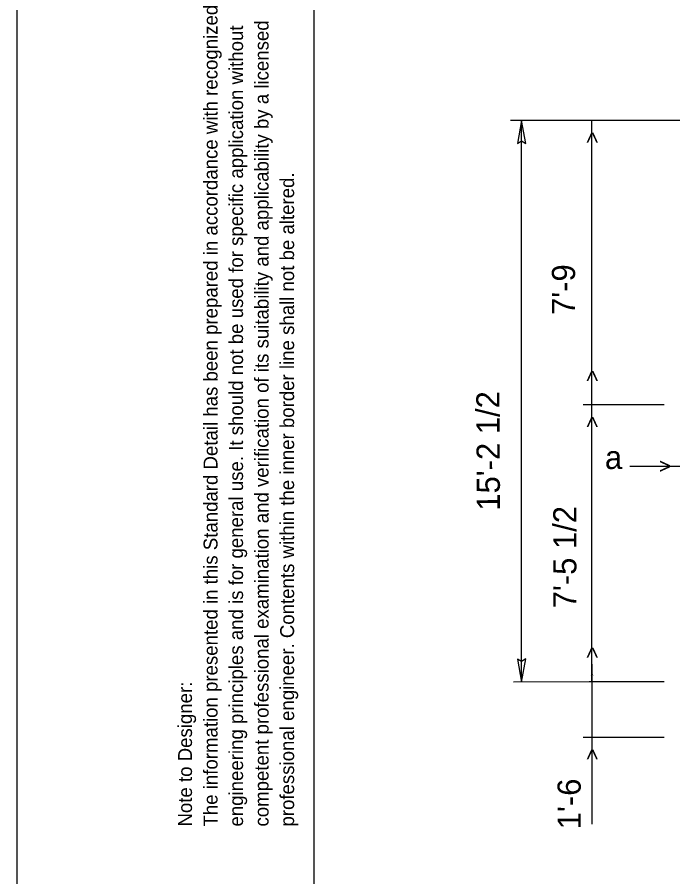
# Model space of a CAD drawing. Extents: x -0.08 to 2.83, y -0.03 to 1.92.
# Drawn here: x 0 to 0.368, y 0.5669 to 1.0496 of the extents above; entities that cross this region are included whole.
import ezdxf

# ---------------------------------------------------------------- set-up
doc = ezdxf.new("R2010")
doc.units = 0
for name, color, linetype in [('54', 7, 'Continuous'), ('55', 7, 'Continuous'), ('57', 7, 'Continuous'), ('63', 7, 'Continuous')]:
    doc.layers.add(name, color=color, linetype=linetype)

msp = doc.modelspace()

# ---------------------------------------------------------------- linework, layer by layer
at = {"layer": '54'}
for points in [[(0.28311, 0.99159), (0.28073, 0.97859), (0.28311, 0.9801), (0.28551, 0.97874)], [(0.28311, 0.67625), (0.28548, 0.68924), (0.28311, 0.68773), (0.28071, 0.68909)]]:
    msp.add_lwpolyline(points, close=True, dxfattribs=at)
at = {"layer": '55'}
for p, q in [((0.79701, 0.99159), (0.27695, 0.99159)), ((0.28311, 0.67625), (0.28311, 0.99159)), ((0.3226, 0.83186), (0.3226, 0.99159)), ((0.36318, 0.83186), (0.31772, 0.83186)), ((0.3226, 0.67649), (0.3226, 0.83186)), ((0.34383, 0.79741), (0.41597, 0.79741)), ((0.3226, 0.68624), (0.3226, 0.67649)), ((0.32096, 0.67644), (0.27858, 0.67623)), ((0.36318, 0.67649), (0.32098, 0.67649)), ((0.32259, 0.67645), (0.3226, 0.64524)), ((0.36318, 0.64524), (0.31772, 0.64524)), ((0.3226, 0.64524), (0.3226, 0.59643))]:
    msp.add_line(p, q, dxfattribs=at)
at = {"layer": '63'}
msp.add_line((0, 0), (0, 1.83333), dxfattribs=at)
msp.add_lwpolyline([(0.16668, 0.06244), (0.16668, 1.77077), (2.72918, 1.77077), (2.72918, 0.10411), (2.56251, 0.10411), (2.56251, 0.14578), (2.07387, 0.14578), (2.07387, 0.06244)], close=True, dxfattribs=at)

# ---------------------------------------------------------------- texts
at = {"layer": '55'}
for s, height, rotation, p in [('The information presented in this Standard Detail has been prepared in accordance with recognized', 0.0078167, 90, (0.11243, 0.59517)), ('engineering principles and is for general use. It should not be used for specific application without', 0.00781665, 90, (0.12676, 0.59517)), ('competent professional examination and verification of its suitability and applicability by a licensed', 0.00781665, 90, (0.14108, 0.59517)), ('>', 0.00863, 90, (0.3269, 0.97859)), ('professional engineer. Contents within the inner border line shall not be altered.', 0.0078167, 90, (0.15541, 0.59517)), ("7'-9 ", 0.013, 90, (0.31311, 0.88239)), ('>', 0.00863, 90, (0.3269, 0.84481)), ("15'-2 1/2", 0.013, 90.2938, (0.27099, 0.77253)), ('>', 0.00863, 90, (0.3269, 0.81886)), ("7'-5 1/2", 0.013, 90, (0.31388, 0.71769)), ('>', 0.00863, 90, (0.3269, 0.68944)), ('>', 0.00216, 90, (0.32368, 0.67974)), ('Note to Designer:', 0.0078167, 90, (0.09811, 0.59517)), ('>', 0.00863, 90, (0.3269, 0.63224)), ("1'-6 ", 0.013, 90, (0.31628, 0.59364))]:
    msp.add_text(s, height=height, rotation=rotation, dxfattribs=at).set_placement(p)
msp.add_text('>', height=0.00868, dxfattribs=at).set_placement((0.36018, 0.79331))
msp.add_text('>', height=0.00868, dxfattribs=at).set_placement((0.36018, 0.79331))
at = {"layer": '57'}
msp.add_text('a', height=0.01302, dxfattribs=at).set_placement((0.32987, 0.7959))

doc.saveas('drawing.dxf')
